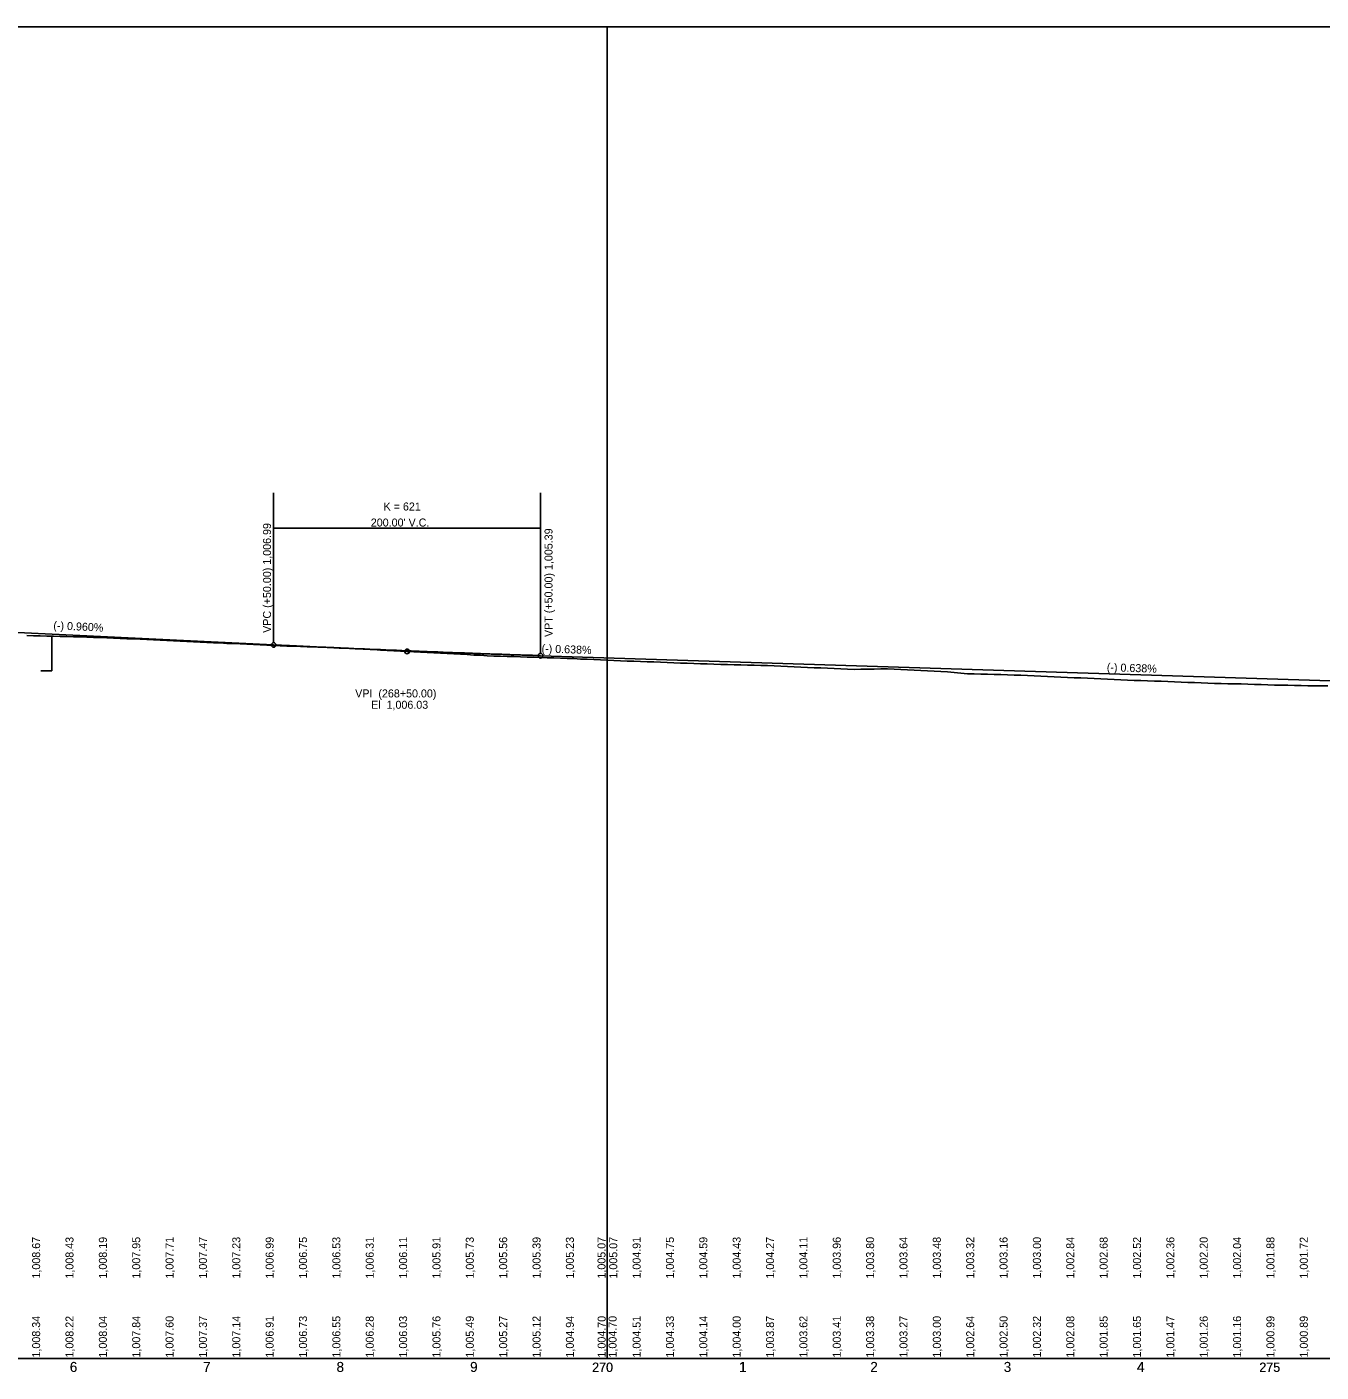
# Model space of a CAD drawing. Extents: x 1608361 to 16979326, y 1092015 to 12565288.
# Drawn here: x 16975551 to 16976521, y 12564278 to 12565286 of the extents above; entities that cross this region are included whole.
import ezdxf

# ---------------------------------------------------------------- set-up
doc = ezdxf.new("R2010")
doc.units = 0
for name, color, linetype in [('Default', 7, 'Continuous'), ('points EP', 7, 'Continuous'), ('RD_DDB_EX_Tx', 7, 'Continuous'), ('RD_EX_Fence_ChLk', 7, 'Continuous'), ('RD_EX_H2O', 7, 'Continuous'), ('RD_EX_RW_Approx', 7, 'Continuous'), ('RD_EX_SU_Water', 7, 'Continuous'), ('RD_EX_UT', 7, 'Continuous'), ('RD_HC_TX_Rel_Sta50', 7, 'Continuous'), ('RD_PD_Final_TX', 7, 'Continuous'), ('TEXT2', 7, 'Continuous')]:
    doc.layers.add(name, color=color, linetype=linetype)

msp = doc.modelspace()

# ---------------------------------------------------------------- linework, layer by layer
at = {"layer": 'Default'}
for points in [[(16974485.6, 12564287.8), (16975985.6, 12564287.8), (16975985.6, 12565286), (16974485.6, 12565286)], [(16975985.6, 12564287.8), (16977485.6, 12564287.8), (16977485.6, 12565286), (16975985.6, 12565286)]]:
    msp.add_lwpolyline(points, close=True, dxfattribs=at)
at = {"layer": 'RD_DDB_EX_Tx'}
for p, q in [((16975569.4, 12564803.3), (16975569.4, 12564829.1)), ((16975561.2, 12564803.3), (16975569.4, 12564803.3))]:
    msp.add_line(p, q, dxfattribs=at)
at = {"layer": 'RD_EX_Fence_ChLk'}
for p, q in [((16975735.6, 12564936.7), (16975735.6, 12564824.5)), ((16975935.6, 12564936.7), (16975935.6, 12564816.5)), ((16975735.6, 12564910.2), (16975935.6, 12564910.2))]:
    msp.add_line(p, q, dxfattribs=at)
for centre in [(16975735.6, 12564822.7), (16975935.6, 12564814.7)]:
    msp.add_circle(centre, 1.75, dxfattribs=at)
at = {"layer": 'RD_EX_H2O'}
for points in [[(16975550.6, 12564829.7), (16975555.6, 12564829.6), (16975560.6, 12564829.5), (16975565.6, 12564829.4), (16975570.6, 12564829.3), (16975575.6, 12564829.1), (16975580.6, 12564829), (16975585.6, 12564828.9), (16975590.6, 12564828.7), (16975595.6, 12564828.5), (16975600.6, 12564828.3), (16975605.6, 12564828.2), (16975610.6, 12564828), (16975615.6, 12564827.8), (16975620.6, 12564827.6), (16975625.6, 12564827.4), (16975630.6, 12564827.2), (16975635.6, 12564827), (16975640.6, 12564826.7), (16975645.6, 12564826.5), (16975650.6, 12564826.3), (16975655.6, 12564826), (16975660.6, 12564825.8), (16975665.6, 12564825.6), (16975670.6, 12564825.3), (16975675.6, 12564825.1), (16975680.6, 12564824.9), (16975685.6, 12564824.6), (16975690.6, 12564824.4), (16975695.6, 12564824.2), (16975700.6, 12564823.9), (16975705.6, 12564823.7), (16975710.6, 12564823.5), (16975715.6, 12564823.2), (16975720.6, 12564823), (16975725.6, 12564822.8), (16975730.6, 12564822.6), (16975735.6, 12564822.3), (16975740.6, 12564822.1), (16975745.6, 12564821.9), (16975750.6, 12564821.8), (16975755.6, 12564821.6), (16975760.6, 12564821.4), (16975765.6, 12564821.2), (16975770.6, 12564821.1), (16975775.6, 12564820.9), (16975780.6, 12564820.7), (16975785.6, 12564820.5), (16975790.6, 12564820.4), (16975795.6, 12564820.1), (16975800.6, 12564819.8), (16975805.6, 12564819.5), (16975810.6, 12564819.2), (16975815.6, 12564818.9), (16975820.6, 12564818.6), (16975825.6, 12564818.3), (16975830.6, 12564818), (16975835.6, 12564817.9), (16975840.6, 12564817.7), (16975845.6, 12564817.4), (16975850.6, 12564817.1), (16975855.6, 12564816.8), (16975860.6, 12564816.6), (16975865.6, 12564816.3), (16975870.6, 12564816), (16975875.6, 12564815.8), (16975880.6, 12564815.5), (16975885.6, 12564815.2), (16975890.6, 12564815), (16975895.6, 12564814.7), (16975900.6, 12564814.4), (16975905.6, 12564814.3), (16975910.6, 12564814.1), (16975915.6, 12564814), (16975920.6, 12564813.8), (16975925.6, 12564813.7), (16975930.6, 12564813.5), (16975935.6, 12564813.4), (16975940.6, 12564813.2), (16975945.6, 12564813), (16975950.6, 12564812.9), (16975955.6, 12564812.7), (16975960.6, 12564812.5), (16975965.6, 12564812.2), (16975970.6, 12564812), (16975975.6, 12564811.8), (16975980.6, 12564811.5), (16975985.6, 12564811.3)], [(16975985.6, 12564811.3), (16975990.6, 12564811.1), (16975995.6, 12564810.9), (16976000.6, 12564810.7), (16976005.6, 12564810.5), (16976010.6, 12564810.3), (16976015.6, 12564810.1), (16976020.6, 12564810), (16976025.6, 12564809.8), (16976030.6, 12564809.6), (16976035.6, 12564809.4), (16976040.6, 12564809.2), (16976045.6, 12564809), (16976050.6, 12564808.9), (16976055.6, 12564808.7), (16976060.6, 12564808.5), (16976065.6, 12564808.3), (16976070.6, 12564808.2), (16976075.6, 12564808.1), (16976080.6, 12564807.9), (16976085.6, 12564807.8), (16976090.6, 12564807.7), (16976095.6, 12564807.5), (16976100.6, 12564807.4), (16976105.6, 12564807.3), (16976110.6, 12564807.2), (16976115.6, 12564806.9), (16976120.6, 12564806.7), (16976125.6, 12564806.4), (16976130.6, 12564806.2), (16976135.6, 12564805.9), (16976140.6, 12564805.7), (16976145.6, 12564805.5), (16976150.6, 12564805.3), (16976155.6, 12564805), (16976160.6, 12564804.8), (16976165.6, 12564804.6), (16976170.6, 12564804.4), (16976175.6, 12564804.5), (16976180.6, 12564804.6), (16976185.6, 12564804.7), (16976190.6, 12564804.8), (16976195.6, 12564804.8), (16976200.6, 12564804.5), (16976205.6, 12564804.3), (16976210.6, 12564804.1), (16976215.6, 12564803.9), (16976220.6, 12564803.6), (16976225.6, 12564803.3), (16976230.6, 12564803.1), (16976235.6, 12564802.8), (16976240.6, 12564802.5), (16976245.6, 12564802.1), (16976250.6, 12564801.6), (16976255.6, 12564801.2), (16976260.6, 12564801), (16976265.6, 12564800.9), (16976270.6, 12564800.8), (16976275.6, 12564800.6), (16976280.6, 12564800.5), (16976285.6, 12564800.3), (16976290.6, 12564800.2), (16976295.6, 12564800), (16976300.6, 12564799.9), (16976305.6, 12564799.6), (16976310.6, 12564799.4), (16976315.6, 12564799.2), (16976320.6, 12564798.9), (16976325.6, 12564798.6), (16976330.6, 12564798.4), (16976335.6, 12564798.2), (16976340.6, 12564798), (16976345.6, 12564797.8), (16976350.6, 12564797.5), (16976355.6, 12564797.3), (16976360.6, 12564797.1), (16976365.6, 12564796.8), (16976370.6, 12564796.6), (16976375.6, 12564796.4), (16976380.6, 12564796.2), (16976385.6, 12564796.1), (16976390.6, 12564795.9), (16976395.6, 12564795.7), (16976400.6, 12564795.5), (16976405.6, 12564795.3), (16976410.6, 12564795.1), (16976415.6, 12564794.9), (16976420.6, 12564794.7), (16976425.6, 12564794.5), (16976430.6, 12564794.3), (16976435.6, 12564794.1), (16976440.6, 12564793.9), (16976445.6, 12564793.8), (16976450.6, 12564793.7), (16976455.6, 12564793.7), (16976460.6, 12564793.6), (16976465.6, 12564793.4), (16976470.6, 12564793.2), (16976475.6, 12564793), (16976480.6, 12564792.9), (16976485.6, 12564792.7)], [(16976485.6, 12564792.7), (16976490.6, 12564792.6), (16976495.6, 12564792.5), (16976500.6, 12564792.4), (16976505.6, 12564792.3), (16976510.6, 12564792.2), (16976515.6, 12564792.2), (16976520.6, 12564792.1), (16976525.6, 12564792)]]:
    msp.add_lwpolyline(points, dxfattribs=at)
at = {"layer": 'RD_EX_RW_Approx'}
for p, q in [((16975745.7, 12564822.2), (16975833.8, 12564818)), ((16975925.5, 12564815.1), (16975837.3, 12564817.9))]:
    msp.add_line(p, q, dxfattribs=at)
msp.add_circle((16975835.6, 12564817.9), 1.75, dxfattribs=at)
at = {"layer": 'RD_EX_UT'}
msp.add_line((16972985.6, 12564287.8), (16978789.9, 12564287.8), dxfattribs=at)
at = {"layer": 'RD_HC_TX_Rel_Sta50'}
for p, q in [((16975445.6, 12564836.7), (16975735.6, 12564822.7)), ((16975935.6, 12564814.7), (16976875.6, 12564784.8))]:
    msp.add_line(p, q, dxfattribs=at)
msp.add_spline([(16975735.6, 12564822.7), (16975739.6, 12564822.5), (16975743.6, 12564822.4), (16975747.6, 12564822.2), (16975751.6, 12564822), (16975755.6, 12564821.8), (16975759.6, 12564821.6), (16975763.6, 12564821.4), (16975767.6, 12564821.2), (16975771.6, 12564821.1), (16975775.6, 12564820.9), (16975779.6, 12564820.7), (16975783.6, 12564820.5), (16975787.6, 12564820.3), (16975791.6, 12564820.2), (16975795.6, 12564820), (16975799.6, 12564819.8), (16975803.6, 12564819.7), (16975807.6, 12564819.5), (16975811.6, 12564819.3), (16975815.6, 12564819.2), (16975819.6, 12564819), (16975823.6, 12564818.8), (16975827.6, 12564818.7), (16975831.6, 12564818.5), (16975835.6, 12564818.3), (16975839.6, 12564818.2), (16975843.6, 12564818), (16975847.6, 12564817.9), (16975851.6, 12564817.7), (16975855.6, 12564817.6), (16975859.6, 12564817.4), (16975863.6, 12564817.2), (16975867.6, 12564817.1), (16975871.6, 12564816.9), (16975875.6, 12564816.8), (16975879.6, 12564816.7), (16975883.6, 12564816.5), (16975887.6, 12564816.4), (16975891.6, 12564816.2), (16975895.6, 12564816.1), (16975899.6, 12564815.9), (16975903.6, 12564815.8), (16975907.6, 12564815.7), (16975911.6, 12564815.5), (16975915.6, 12564815.4), (16975919.6, 12564815.3), (16975923.6, 12564815.1), (16975927.6, 12564815), (16975931.6, 12564814.9), (16975935.6, 12564814.7)], degree=3, dxfattribs=at)

# ---------------------------------------------------------------- texts
at = {"layer": 'points EP'}
for s, rotation, p in [('(-) 0.960%', 357.2519, (16975570.4, 12564834.5)), ('(-) 0.638%', 358.1729, (16975936.3, 12564817.1)), ('(-) 0.638%', 358.1729, (16976359.9, 12564803.1))]:
    msp.add_text(s, height=6, rotation=rotation, dxfattribs=at).set_placement(p)
at = {"layer": 'RD_EX_Fence_ChLk'}
for s, p in [('K = 621', (16975818, 12564923.5)), ("200.00' V.C.", (16975808.4, 12564911.5))]:
    msp.add_text(s, height=6, dxfattribs=at).set_placement(p)
for s, p in [('VPC (+50.00) 1,006.99', (16975733.6, 12564831.8)), ('VPT (+50.00) 1,005.39', (16975944.6, 12564828.7))]:
    msp.add_text(s, height=6, rotation=90, dxfattribs=at).set_placement(p)
at = {"layer": 'RD_EX_RW_Approx'}
for s, p in [('VPI  (268+50.00)', (16975796.7, 12564783.4)), ('El  1,006.03', (16975808.6, 12564774.9))]:
    msp.add_text(s, height=6, dxfattribs=at).set_placement(p)
at = {"layer": 'RD_EX_SU_Water'}
for s, p in [('1,008.67', (16975560.6, 12564347.8)), ('1,008.43', (16975585.6, 12564347.8)), ('1,008.19', (16975610.6, 12564347.8)), ('1,007.95', (16975635.6, 12564347.8)), ('1,007.71', (16975660.6, 12564347.8)), ('1,007.47', (16975685.6, 12564347.8)), ('1,007.23', (16975710.6, 12564347.8)), ('1,006.99', (16975735.6, 12564347.8)), ('1,006.75', (16975760.6, 12564347.8)), ('1,006.53', (16975785.6, 12564347.8)), ('1,006.31', (16975810.6, 12564347.8)), ('1,006.11', (16975835.6, 12564347.8)), ('1,005.91', (16975860.6, 12564347.8)), ('1,005.73', (16975885.6, 12564347.8)), ('1,005.56', (16975910.6, 12564347.8)), ('1,005.39', (16975935.6, 12564347.8)), ('1,005.23', (16975960.6, 12564347.8)), ('1,005.07', (16975984.3, 12564347.8)), ('1,005.07', (16975993.1, 12564347.8)), ('1,004.91', (16976010.6, 12564347.8)), ('1,004.75', (16976035.6, 12564347.8)), ('1,004.59', (16976060.6, 12564347.8)), ('1,004.43', (16976085.6, 12564347.8)), ('1,004.27', (16976110.6, 12564347.8)), ('1,004.11', (16976135.6, 12564347.8)), ('1,003.96', (16976160.6, 12564347.8)), ('1,003.80', (16976185.6, 12564347.8)), ('1,003.64', (16976210.6, 12564347.8)), ('1,003.48', (16976235.6, 12564347.8)), ('1,003.32', (16976260.6, 12564347.8)), ('1,003.16', (16976285.6, 12564347.8)), ('1,003.00', (16976310.6, 12564347.8)), ('1,002.84', (16976335.6, 12564347.8)), ('1,002.68', (16976360.6, 12564347.8)), ('1,002.52', (16976385.6, 12564347.8)), ('1,002.36', (16976410.6, 12564347.8)), ('1,002.20', (16976435.6, 12564347.8)), ('1,002.04', (16976460.6, 12564347.8)), ('1,001.88', (16976485.6, 12564347.8)), ('1,001.72', (16976510.6, 12564347.8))]:
    msp.add_text(s, height=6, rotation=90, dxfattribs=at).set_placement(p)
at = {"layer": 'RD_PD_Final_TX'}
for s, height, p in [('6', 7.5, (16975582.8, 12564277.8)), ('6', 7.5, (16975582.9, 12564277.8)), ('7', 7.5, (16975682.7, 12564277.8)), ('7', 7.5, (16975682.8, 12564277.8)), ('8', 7.5, (16975782.7, 12564277.8)), ('8', 7.5, (16975782.8, 12564277.8)), ('9', 7.5, (16975882.8, 12564277.8)), ('9', 7.5, (16975882.9, 12564277.8)), ('270', 7, (16975974.2, 12564277.8)), ('270', 7, (16975974.4, 12564277.8)), ('1', 7.5, (16976084.2, 12564277.8)), ('1', 7.5, (16976084.6, 12564277.8)), ('2', 7.5, (16976182.7, 12564277.8)), ('2', 7.5, (16976182.8, 12564277.8)), ('3', 7.5, (16976282.7, 12564277.8)), ('3', 7.5, (16976282.8, 12564277.8)), ('4', 7.5, (16976382.5, 12564277.8)), ('4', 7.5, (16976382.8, 12564277.8)), ('275', 7, (16976474.2, 12564277.8)), ('275', 7, (16976474.4, 12564277.8))]:
    msp.add_text(s, height=height, dxfattribs=at).set_placement(p)
at = {"layer": 'TEXT2'}
for s, p in [('1,008.34', (16975560.6, 12564288.6)), ('1,008.22', (16975585.6, 12564288.6)), ('1,008.04', (16975610.6, 12564288.6)), ('1,007.84', (16975635.6, 12564288.6)), ('1,007.60', (16975660.6, 12564288.6)), ('1,007.37', (16975685.6, 12564288.6)), ('1,007.14', (16975710.6, 12564288.6)), ('1,006.91', (16975735.6, 12564288.6)), ('1,006.73', (16975760.6, 12564288.6)), ('1,006.55', (16975785.6, 12564288.6)), ('1,006.28', (16975810.6, 12564288.6)), ('1,006.03', (16975835.6, 12564288.6)), ('1,005.76', (16975860.6, 12564288.6)), ('1,005.49', (16975885.6, 12564288.6)), ('1,005.27', (16975910.6, 12564288.6)), ('1,005.12', (16975935.6, 12564288.6)), ('1,004.94', (16975960.6, 12564288.6)), ('1,004.70', (16975984.4, 12564288.6)), ('1,004.70', (16975992.6, 12564288.6)), ('1,004.51', (16976010.6, 12564288.6)), ('1,004.33', (16976035.6, 12564288.6)), ('1,004.14', (16976060.6, 12564288.6)), ('1,004.00', (16976085.6, 12564288.6)), ('1,003.87', (16976110.6, 12564288.6)), ('1,003.62', (16976135.6, 12564288.6)), ('1,003.41', (16976160.6, 12564288.6)), ('1,003.38', (16976185.6, 12564288.6)), ('1,003.27', (16976210.6, 12564288.6)), ('1,003.00', (16976235.6, 12564288.6)), ('1,002.64', (16976260.6, 12564288.6)), ('1,002.50', (16976285.6, 12564288.6)), ('1,002.32', (16976310.6, 12564288.6)), ('1,002.08', (16976335.6, 12564288.6)), ('1,001.85', (16976360.6, 12564288.6)), ('1,001.65', (16976385.6, 12564288.6)), ('1,001.47', (16976410.6, 12564288.6)), ('1,001.26', (16976435.6, 12564288.6)), ('1,001.16', (16976460.6, 12564288.6)), ('1,000.99', (16976485.6, 12564288.6)), ('1,000.89', (16976510.6, 12564288.6))]:
    msp.add_text(s, height=6, rotation=90, dxfattribs=at).set_placement(p)

doc.saveas('drawing.dxf')
